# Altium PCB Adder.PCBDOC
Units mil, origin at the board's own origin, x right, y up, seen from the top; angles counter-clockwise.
Board outline 6000 x 4000 mil, 2 copper layers (Top Layer, Bottom Layer); 6 components, 16 nets, 48 pads, 0 vias.
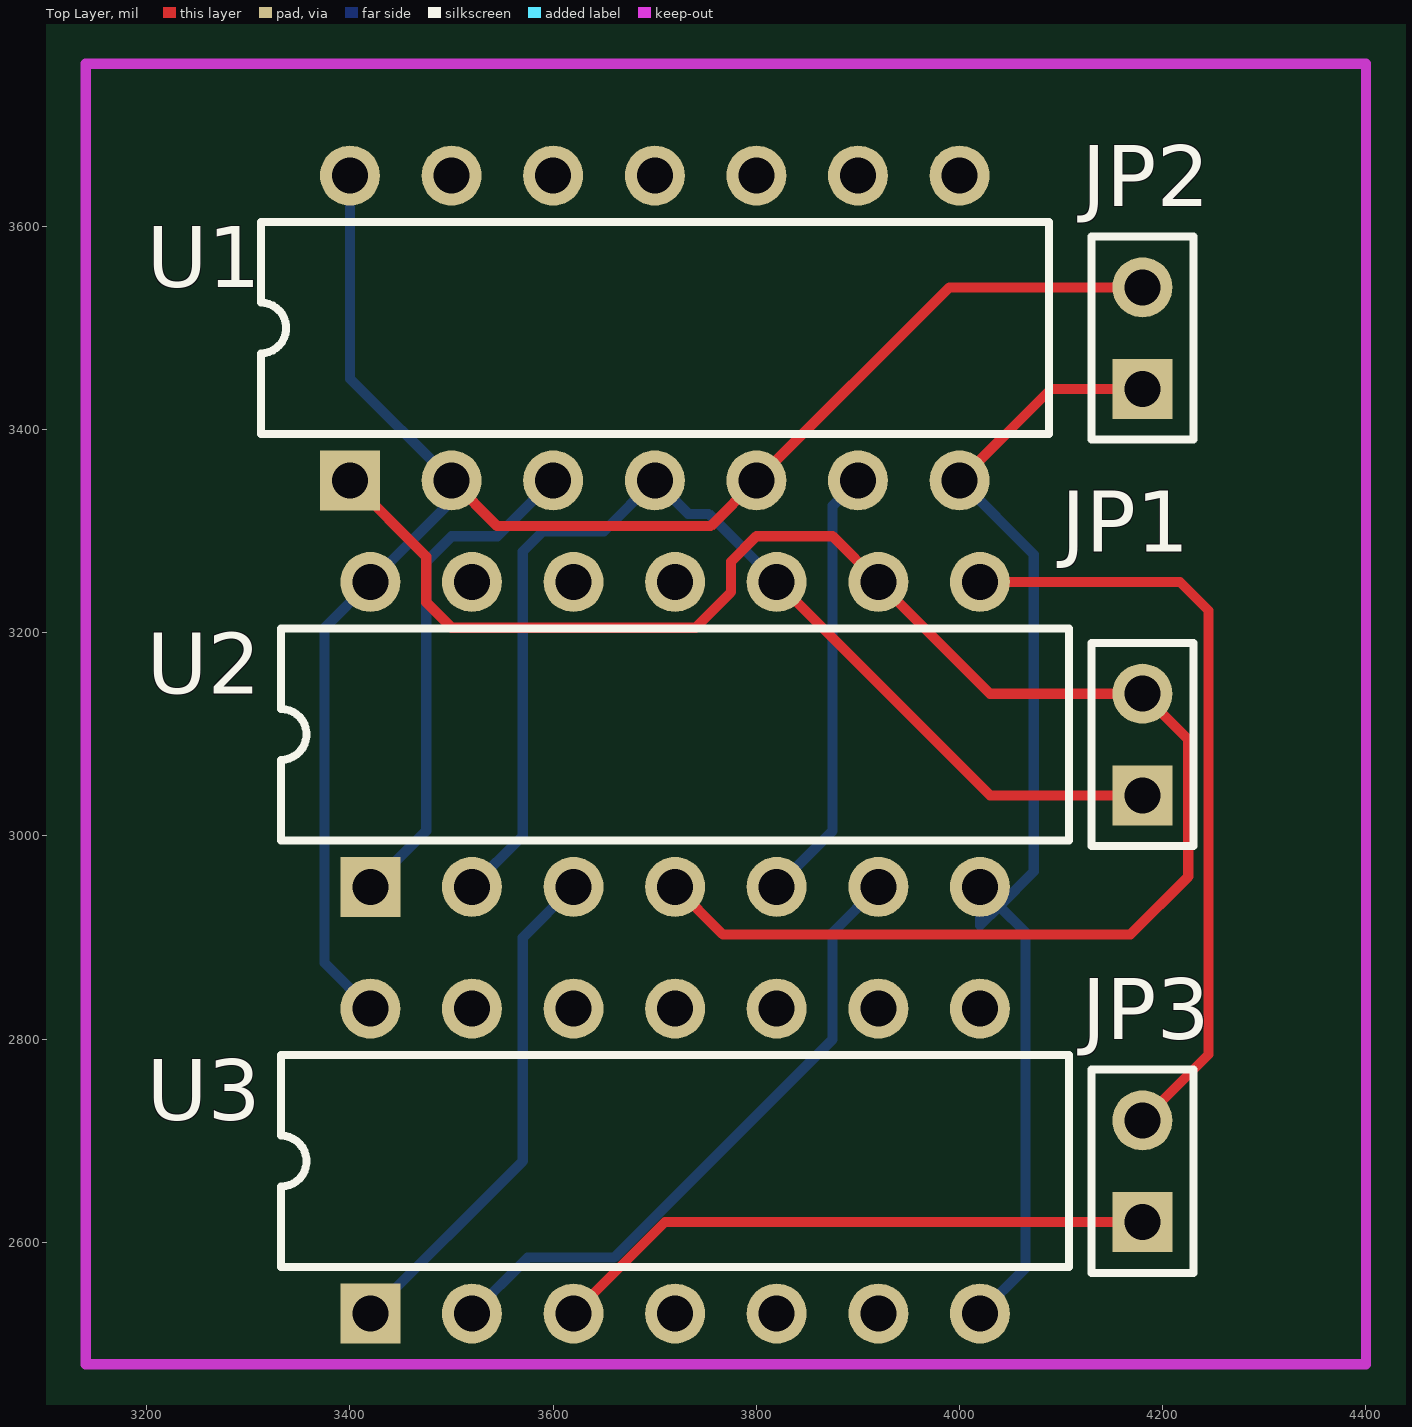
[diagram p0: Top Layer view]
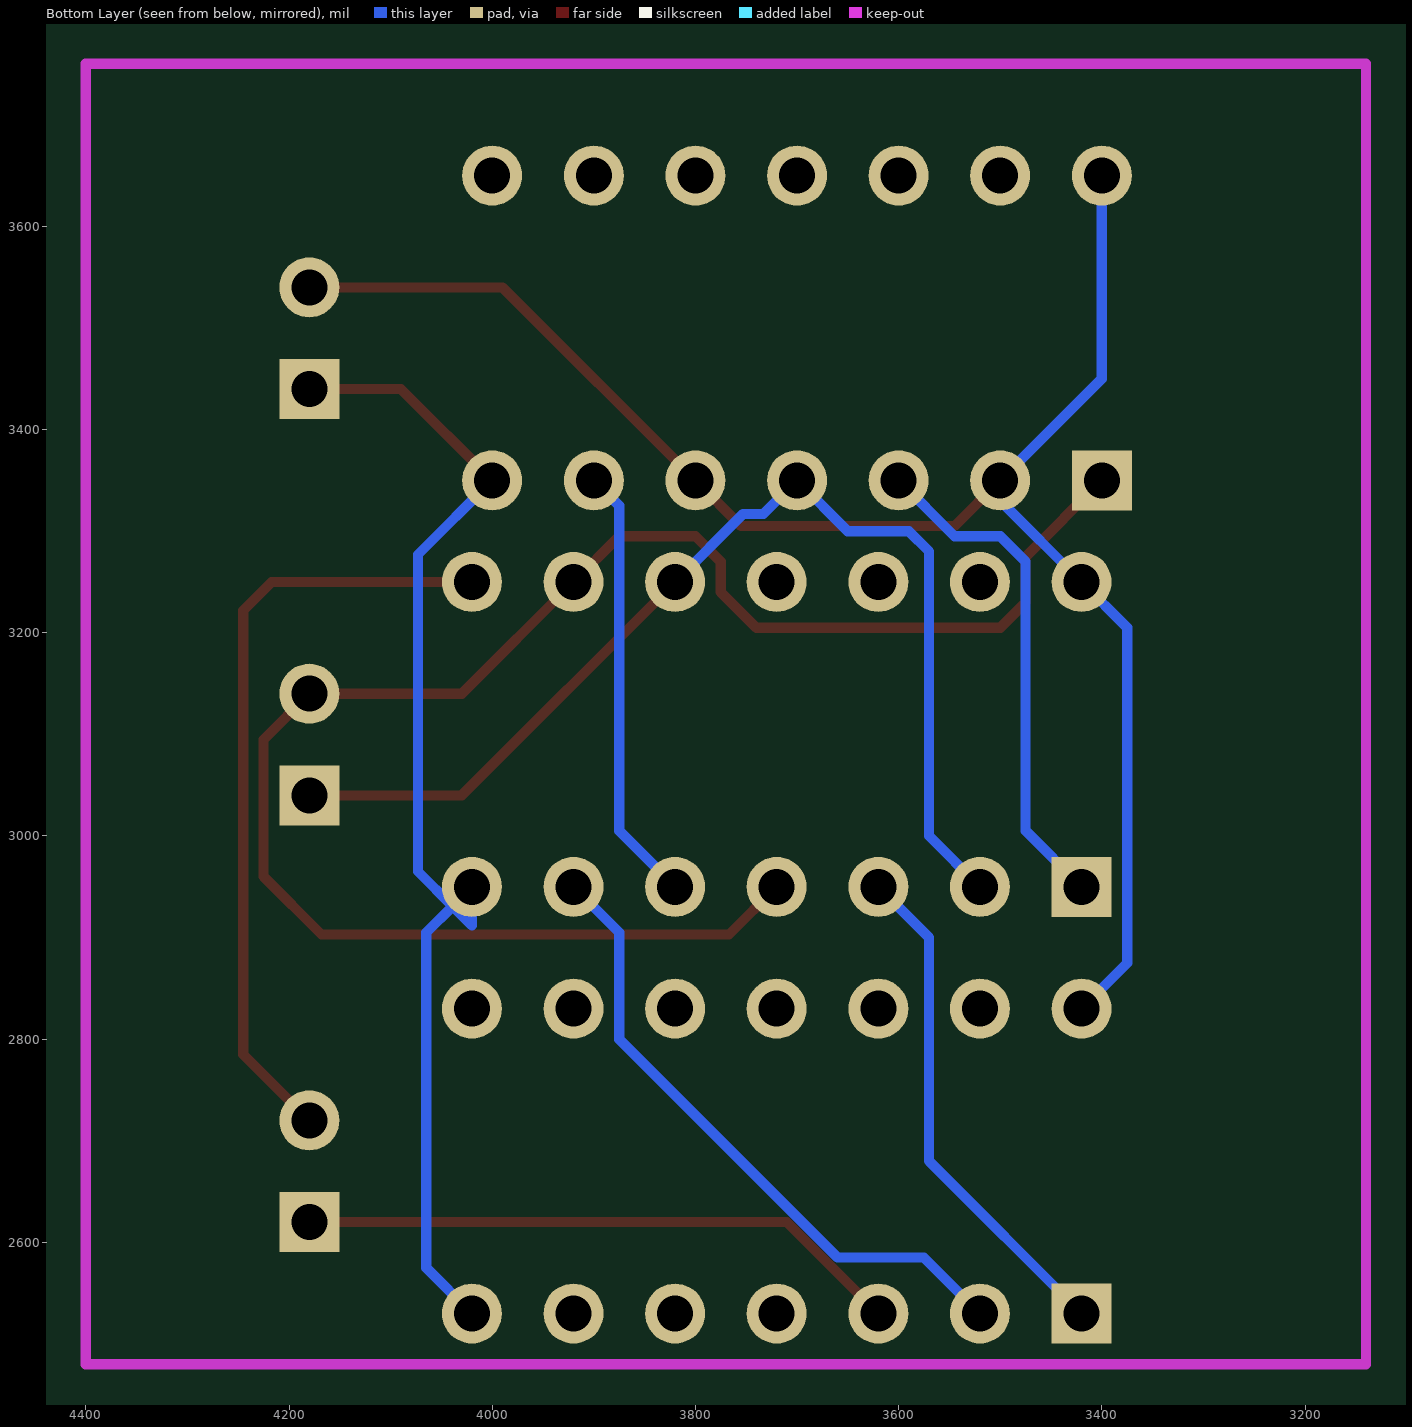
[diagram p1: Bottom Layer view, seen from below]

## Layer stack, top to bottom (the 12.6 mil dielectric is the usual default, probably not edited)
Top Layer: signal copper 1.4
Dielectric: dielectric 12.6, FR-4, Dk 4.8
Bottom Layer: signal copper 1.4

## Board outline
1000,1000 7000,1000 7000,5000 1000,5000

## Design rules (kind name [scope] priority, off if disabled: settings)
Clearance [All] p1: gap=10
ComponentClearance [All] p1: gap=10 collisioncheckmode=0
PolygonConnect [All] p1: connectstyle=Relief reliefconductorwidth=10 reliefentries=4 polygonreliefangle="90 Angle"
RoutingLayers [All] p1: top layer=Horizontal bottom layer=Vertical
RoutingVias [All] p1: holewidth=28 width=50 viastyle="Through Hole" minholewidth=28 minwidth=50 maxholewidth=28 maxwidth=50
SolderMaskExpansion [All] p1: expansion=4
TestPointUsage [All] p1: valid=0 allowmultiple=FALSE
Testpoint [All] p1: side=15 testpointundercomponent=TRUE minsize=40 maxsize=100 preferedsize=60 minholesize=0 maxholesize=40 preferedholesize=32 testpointgrid=1 style=1023 order=-539222988
Width [All] p1: maxlimit=10 minlimit=10 preferedwidth=10
16 further rules are at their usual default settings.

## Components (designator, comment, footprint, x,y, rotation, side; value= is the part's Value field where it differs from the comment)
JP1 "Header 2" HDR1X2 4180,3040 r90 top
JP2 "Header 2" HDR1X2 4180,3440 r90 top
JP3 "Header 2" HDR1X2 4180,2620 r90 top
U1 "SN74LS00N" DIP-14/D19.7 3700,3500 r0 top
U2 "SN74ALS08N" DIP-14/D19.7 3720,3100 r0 top
U3 "SN74LS32N" DIP-14/D19.7 3720,2680 r0 top

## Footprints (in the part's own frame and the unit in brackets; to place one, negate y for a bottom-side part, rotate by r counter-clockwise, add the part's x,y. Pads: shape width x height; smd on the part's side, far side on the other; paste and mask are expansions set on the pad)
DIP-14/D19.7 [mm]
  rect 1.5x1.5 hole 0.9: 1(-7.62,-3.81)
  round 1.5 hole 0.9: 2(-5.08,-3.81) 3(-2.54,-3.81) 4(0,-3.81) 5(2.54,-3.81) 6(5.08,-3.81) 7(7.62,-3.81) 8(7.62,3.81) 9(5.08,3.81) 10(2.54,3.81) 11(0,3.81) 12(-2.54,3.81) 13(-5.08,3.81) 14(-7.62,3.81)
  silkscreen extent -9.85,-2.65 9.85,2.65
HDR1X2 [mm]
  rect 1.5x1.5 hole 0.9: 1(0,0)
  round 1.5 hole 0.9: 2(2.54,0)
  silkscreen extent -1.27,-1.27 3.81,1.27

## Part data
JP1 JP2 JP3: "Header, 2-Pin"
U1: "Quadruple 2-Input Positive-NAND Gate"
U2: "Quadruple 2-Input Positive-AND Gate"
U3: "Quadruple 2-Input Positive-OR Gate"

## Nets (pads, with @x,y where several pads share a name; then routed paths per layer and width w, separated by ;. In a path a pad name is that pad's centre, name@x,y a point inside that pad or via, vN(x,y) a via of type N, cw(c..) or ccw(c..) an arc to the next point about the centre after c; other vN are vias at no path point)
GND: JP2.1 U1.7 U2.7 U3.7 | length 1175.9
  Top Layer w10: U1.7 4090,3440 JP2.1
  Bottom Layer w10: U1.7 4073,3277 4073,2965 U2.7@4039,2931 ; U3.7 4065,2575 4065,2905 U2.7@4039,2931 ; U2.7 4020,2912 U2.7@4039,2931
NetJP1_1: JP1.1 U1.4 U2.2 U2.10 | length 1118.1
  Top Layer w10: U2.10 4030,3040 JP1.1
  Bottom Layer w10: U2.2 3570,3000 3570,3280 3590,3300 3650,3300 U1.4 3733,3317 3753,3317 U2.10
NetJP1_2: JP1.2 U1.1 U2.4 U2.9 | length 1732.2
  Top Layer w10: U1.1 3475,3275 3475,3230 3500,3205 3740,3205 3775,3240 3775,3270 3800,3295 3875,3295 U2.9 4030,3140 JP1.2 4225,3095 4225,2960 4168,2903 3767,2903 U2.4
NetJP2_1: 
NetJP2_2: 
NetJP3_1: JP3.1 U3.3 | length 597.3
  Top Layer w10: U3.3 3710,2620 JP3.1
NetJP3_2: JP3.2 U2.8 | length 765.5
  Top Layer w10: U2.8 4217,3250 4245,3222 4245,2785 JP3.2
NetU1_3: U1.3 U2.1 | length 500.9
  Bottom Layer w10: U2.1 3475,3005 3475,3270 3500,3295 3545,3295 U1.3
NetU1_6: U1.6 U2.5 | length 433.1
  Bottom Layer w10: U2.5 3875,3005 3875,3325 U1.6
NetU2_3: U2.3 U3.1 | length 502.8
  Bottom Layer w10: U3.1 3570,2680 3570,2900 U2.3
NetU2_6: U2.6 U3.2 | length 635.5
  Bottom Layer w10: U3.2 3575,2585 3660,2585 3875,2800 3875,2905 U2.6
NetU?_1: 
NetU?_1: 
NetU?_2: 
NetU?_5: 
VCC: JP2.2 U1.2 U1.5 U1.14 U2.14 U3.14 | length 1727.8
  Top Layer w10: U1.2 3545,3305 3755,3305 U1.5 3990,3540 JP2.2
  Bottom Layer w10: U1.14 3400,3450 U1.2 3500,3330 U2.14 3375,3205 3375,2875 U3.14
pads on no net: U1.8 U1.9 U1.10 U1.11 U1.12 U1.13 U2.11 U2.12 U2.13 U3.4 U3.5 U3.6 U3.8 U3.9 U3.10 U3.11 U3.12 U3.13

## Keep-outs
Keep-Out Layer:
  lines w10: 3140,2480 3140,3760 4400,3760 4400,2480 3140,2480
